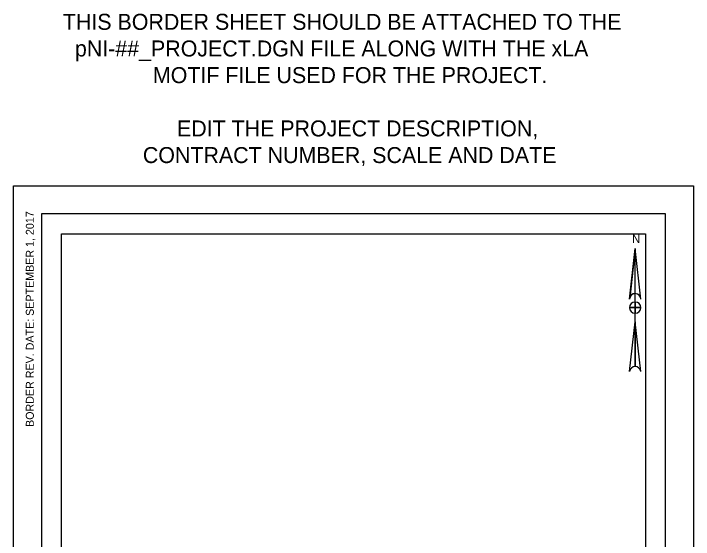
# Model space of a CAD drawing. Extents: x 0 to 8.5, y 0 to 13.2.
# Drawn here: x 0 to 8.5, y 6.58 to 13.15 of the extents above; entities that cross this region are included whole.
import ezdxf

# ---------------------------------------------------------------- set-up
doc = ezdxf.new("R2010")
doc.units = 0
for name, color, linetype in [('BORD-LINE', 7, 'Continuous'), ('NRTH-ARRO', 7, 'Continuous'), ('USER-CLIP', 7, 'Continuous'), ('USER-PAGE', 7, 'Continuous'), ('USER-TEXT', 7, 'Continuous')]:
    doc.layers.add(name, color=color, linetype=linetype)

msp = doc.modelspace()

# ---------------------------------------------------------------- linework, layer by layer
at = {"layer": 'BORD-LINE'}
msp.add_lwpolyline([(0.35, 0.8607), (0.35, 0.35), (8.15, 0.35), (8.15, 10.65), (0.35, 10.65), (0.35, 0.8607)], dxfattribs=at)
at = {"layer": 'NRTH-ARRO'}
for p, q in [((7.7016, 9.5803), (7.7718, 10.213)), ((7.7718, 8.7376), (7.7718, 10.213)), ((7.8421, 9.5803), (7.7718, 10.213)), ((7.7718, 9.4753), (7.7718, 9.5455)), ((7.7016, 9.4753), (7.7718, 9.4753)), ((7.7016, 9.4753), (7.7016, 9.4753)), ((7.7016, 9.4753), (7.7016, 9.4753)), ((7.8421, 9.4753), (7.7718, 9.4753)), ((7.7718, 9.4753), (7.7718, 9.405)), ((7.8421, 9.4753), (7.8421, 9.4753)), ((7.8421, 9.4753), (7.8421, 9.4753)), ((7.7025, 8.6755), (7.7718, 9.2993)), ((7.8412, 8.6755), (7.7718, 9.2993))]:
    msp.add_line(p, q, dxfattribs=at)
for points in [[(7.7718, 9.6505), (7.7718, 9.6505), (7.7718, 10.213), (7.7034, 9.5956)], [(7.7718, 9.5455), (7.7718, 9.4753), (7.8421, 9.4753)], [(7.7718, 9.405), (7.7718, 9.4753), (7.7016, 9.4753), (7.7016, 9.4753)], [(7.7718, 9.405), (7.7718, 9.405)], [(7.8412, 8.6755), (7.7718, 9.2993), (7.7718, 8.7376)]]:
    msp.add_lwpolyline(points, dxfattribs=at)
for centre, radius, start, end in [((7.772, 9.5802), 0.0703, 90, 180), ((7.772, 9.5802), 0.0703, 90.09047, 167.34843), ((7.772, 9.5802), 0.0703, 0, 90), ((7.7718, 9.4753), 0.0703, 90, 180), ((7.7718, 9.4753), 0.0703, 0, 90), ((7.7718, 9.4753), 0.0703, 0.00121, 89.99879), ((7.7718, 9.4753), 0.0703, 180, 270), ((7.7718, 9.4753), 0.0703, 180, 270), ((7.7718, 9.4753), 0.0703, 270, 360), ((7.7718, 8.6678), 0.0698, 6.34387, 173.65613), ((7.7718, 8.6678), 0.0698, 6.34387, 90)]:
    msp.add_arc(centre, radius, start, end, dxfattribs=at)
at = {"layer": 'USER-CLIP'}
msp.add_lwpolyline([(0.6, 10.4), (7.9, 10.4), (7.9, 2.35), (0.6, 2.35)], close=True, dxfattribs=at)
at = {"layer": 'USER-PAGE'}
msp.add_lwpolyline([(0, 11), (8.5, 11), (8.5, 0), (0, 0)], close=True, dxfattribs=at)

# ---------------------------------------------------------------- texts
at = {"layer": 'NRTH-ARRO'}
msp.add_text('N', height=0.105, dxfattribs=at).set_placement((7.7338, 10.2832))
at = {"layer": 'USER-TEXT'}
for s, p in [('THIS BORDER SHEET SHOULD BE ATTACHED TO THE', (0.6158, 12.9498)), ('pNI-##_PROJECT.DGN FILE ALONG WITH THE xLA ', (0.7667, 12.6165)), ('MOTIF FILE USED FOR THE PROJECT.', (1.7418, 12.2833)), ('EDIT THE PROJECT DESCRIPTION, ', (2.0425, 11.6166)), ('CONTRACT NUMBER, SCALE AND DATE', (1.6162, 11.2833))]:
    msp.add_text(s, height=0.2, dxfattribs=at).set_placement(p)
msp.add_text('BORDER REV. DATE: SEPTEMBER 1, 2017', height=0.1, rotation=90, dxfattribs=at).set_placement((0.253, 7.983))

doc.saveas('drawing.dxf')
